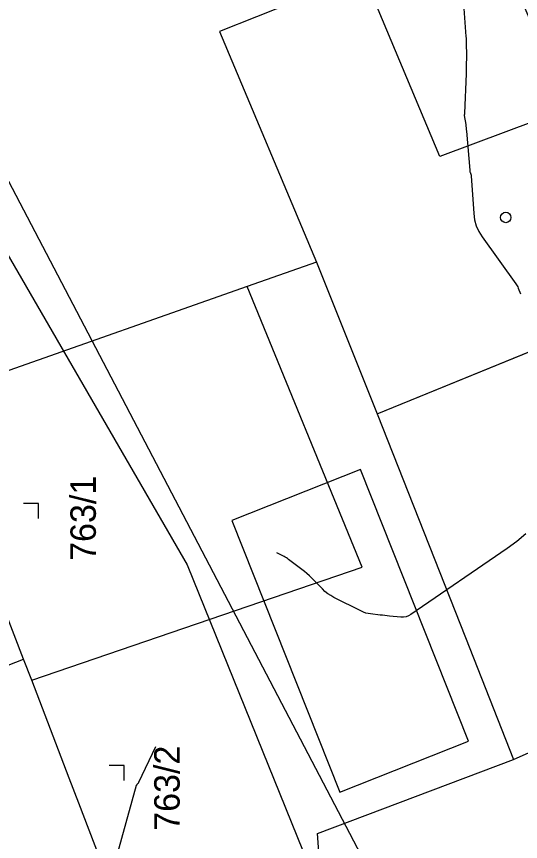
# Model space of a CAD drawing. Extents: x -534481 to -534262, y -1190577 to -1190138.
# Drawn here: x -534420.76 to -534403.93, y -1190505.1 to -1190477.55 of the extents above; entities that cross this region are included whole.
import ezdxf

# ---------------------------------------------------------------- set-up
doc = ezdxf.new("R2010")
doc.units = 0
for name, color, linetype in [('_přístup', 7, 'Continuous'), ('Definiční body', 7, 'Continuous'), ('Polygon budovy', 7, 'Continuous'), ('Polygon parcely', 7, 'Continuous'), ('Vrstva 18', 7, 'Continuous'), ('Vrstva 19', 7, 'Continuous'), ('Vrstva 31', 7, 'Continuous'), ('Vrstva 46', 7, 'Continuous'), ('Vrstva 48', 7, 'Continuous')]:
    doc.layers.add(name, color=color, linetype=linetype)

msp = doc.modelspace()

# ---------------------------------------------------------------- linework, layer by layer
at = {"layer": '_přístup'}
msp.add_lwpolyline([(-534437.347, -1190471.884), (-534433.314, -1190474.1), (-534423.794, -1190480.783), (-534415.053, -1190495.863), (-534409.457, -1190509.706)], dxfattribs=at)
msp.add_lwpolyline([(-534405.667, -1190501.749), (-534409.275, -1190492.679), (-534413.564, -1190494.385), (-534409.956, -1190503.455)], close=True, dxfattribs=at)
at = {"layer": 'Definiční body'}
for p, q in [((-534408.72, -1190490.82), (-534395.25, -1190485.32)), ((-534410.74, -1190485.76), (-534413.05, -1190486.57)), ((-534413.05, -1190486.57), (-534423.85, -1190490.37))]:
    msp.add_line(p, q, dxfattribs=at)
for points in [[(-534410.27, -1190476.57), (-534413.98, -1190478.05), (-534410.74, -1190485.76)], [(-534410.74, -1190485.76), (-534408.96, -1190490.21), (-534408.72, -1190490.82)], [(-534420.25, -1190499.72), (-534409.22, -1190495.94), (-534413.05, -1190486.57)], [(-534420.25, -1190499.72), (-534420.52, -1190499.02), (-534423.85, -1190490.37)], [(-534408.72, -1190490.82), (-534405.77, -1190498.29), (-534404.16, -1190502.37)], [(-534404.16, -1190502.37), (-534398.74, -1190499.95), (-534395.53, -1190498.55)], [(-534417.44, -1190507.05), (-534418.68, -1190503.83), (-534419, -1190502.99), (-534420.25, -1190499.72)], [(-534415.58, -1190511.65), (-534410.34, -1190509.87), (-534410.71, -1190504.84), (-534404.16, -1190502.37)]]:
    msp.add_lwpolyline(points, dxfattribs=at)
at = {"layer": 'Polygon parcely'}
for points in [[(-534413.98, -1190478.05), (-534410.74, -1190485.76), (-534408.96, -1190490.21), (-534408.72, -1190490.82), (-534395.25, -1190485.32), (-534400.89, -1190472.11), (-534405.17, -1190474.16), (-534402.3, -1190480.62), (-534406.62, -1190482.23), (-534409.2, -1190476.06), (-534410.27, -1190476.57)], [(-534435.1, -1190485.93), (-534432.31, -1190492.91), (-534429.79, -1190491.88), (-534429.85, -1190491.74), (-534428.8, -1190491.29), (-534424.88, -1190500.72), (-534420.52, -1190499.02), (-534423.85, -1190490.37), (-534424.32, -1190490.54), (-534427.57, -1190482.9)]]:
    msp.add_lwpolyline(points, close=True, dxfattribs=at)
at = {"layer": 'Vrstva 18'}
msp.add_lwpolyline([(-534416.117, -1190501.942), (-534416.678, -1190503.136), (-534416.683, -1190503.146), (-534416.689, -1190503.155), (-534416.696, -1190503.163), (-534416.704, -1190503.171), (-534416.736, -1190503.202), (-534416.744, -1190503.21), (-534416.75, -1190503.219), (-534416.755, -1190503.229), (-534416.759, -1190503.239), (-534417.74, -1190506.779)], dxfattribs=at)
at = {"layer": 'Vrstva 19'}
for points in [[(-534405.835, -1190477.127), (-534405.752, -1190478.22), (-534405.748, -1190478.281), (-534405.745, -1190478.342), (-534405.742, -1190478.404), (-534405.741, -1190478.465), (-534405.733, -1190478.83), (-534405.733, -1190478.857), (-534405.733, -1190478.859), (-534405.741, -1190479.224), (-534405.742, -1190479.285), (-534405.744, -1190479.347), (-534405.746, -1190479.408), (-534405.748, -1190479.47), (-534405.796, -1190480.777), (-534405.797, -1190480.784), (-534405.797, -1190480.791), (-534405.798, -1190480.798), (-534405.799, -1190480.804), (-534405.804, -1190480.831), (-534405.805, -1190480.838), (-534405.806, -1190480.845), (-534405.806, -1190480.851), (-534405.805, -1190480.858), (-534405.759, -1190481.166), (-534405.752, -1190481.22), (-534405.745, -1190481.274), (-534405.739, -1190481.328), (-534405.734, -1190481.382), (-534405.624, -1190482.691), (-534405.623, -1190482.707), (-534405.62, -1190482.723), (-534405.616, -1190482.738), (-534405.611, -1190482.754), (-534405.59, -1190482.814), (-534405.585, -1190482.829), (-534405.581, -1190482.845), (-534405.579, -1190482.861), (-534405.577, -1190482.877), (-534405.491, -1190484.133), (-534405.463, -1190484.343), (-534405.406, -1190484.543), (-534405.322, -1190484.733), (-534405.211, -1190484.913), (-534404.084, -1190486.485), (-534404.062, -1190486.518), (-534404.042, -1190486.552), (-534404.023, -1190486.587), (-534404.007, -1190486.624), (-534403.927, -1190486.816)], [(-534403.756, -1190494.829), (-534404.054, -1190495.088), (-534404.374, -1190495.324), (-534407.595, -1190497.527), (-534407.671, -1190497.57), (-534407.751, -1190497.599), (-534407.835, -1190497.612), (-534407.922, -1190497.611), (-534408.299, -1190497.576), (-534408.379, -1190497.568), (-534408.459, -1190497.56), (-534408.539, -1190497.551), (-534408.619, -1190497.543), (-534408.939, -1190497.507), (-534409.018, -1190497.494), (-534409.095, -1190497.475), (-534409.17, -1190497.449), (-534409.243, -1190497.416), (-534410.16, -1190496.953), (-534410.265, -1190496.895), (-534410.364, -1190496.829), (-534410.457, -1190496.754), (-534410.545, -1190496.672), (-534410.9, -1190496.309), (-534410.978, -1190496.233), (-534411.058, -1190496.16), (-534411.14, -1190496.089), (-534411.225, -1190496.022), (-534411.671, -1190495.683), (-534411.707, -1190495.656), (-534411.745, -1190495.631), (-534411.784, -1190495.608), (-534411.824, -1190495.586), (-534412.066, -1190495.46)]]:
    msp.add_lwpolyline(points, dxfattribs=at)
at = {"layer": 'Vrstva 31'}
msp.add_lwpolyline([(-534405.695, -1190512.351), (-534434.703, -1190456.89), (-534411.68, -1190394.248)], dxfattribs=at)
at = {"layer": 'Vrstva 46'}
msp.add_circle((-534404.422, -1190484.264), 0.175, dxfattribs=at)
at = {"layer": 'Vrstva 48'}
for p, q in [((-534420.024, -1190493.822), (-534420.524, -1190493.822)), ((-534420.024, -1190494.323), (-534420.024, -1190493.822)), ((-534417.158, -1190502.572), (-534417.658, -1190502.572)), ((-534417.158, -1190503.073), (-534417.158, -1190502.572))]:
    msp.add_line(p, q, dxfattribs=at)

# ---------------------------------------------------------------- texts
at = {"layer": 'Polygon budovy'}
for s, p in [('763/1', (-534418.107, -1190495.734)), ('763/2', (-534415.309, -1190504.747))]:
    msp.add_text(s, height=0.85, rotation=90, dxfattribs=at).set_placement(p)

doc.saveas('drawing.dxf')
